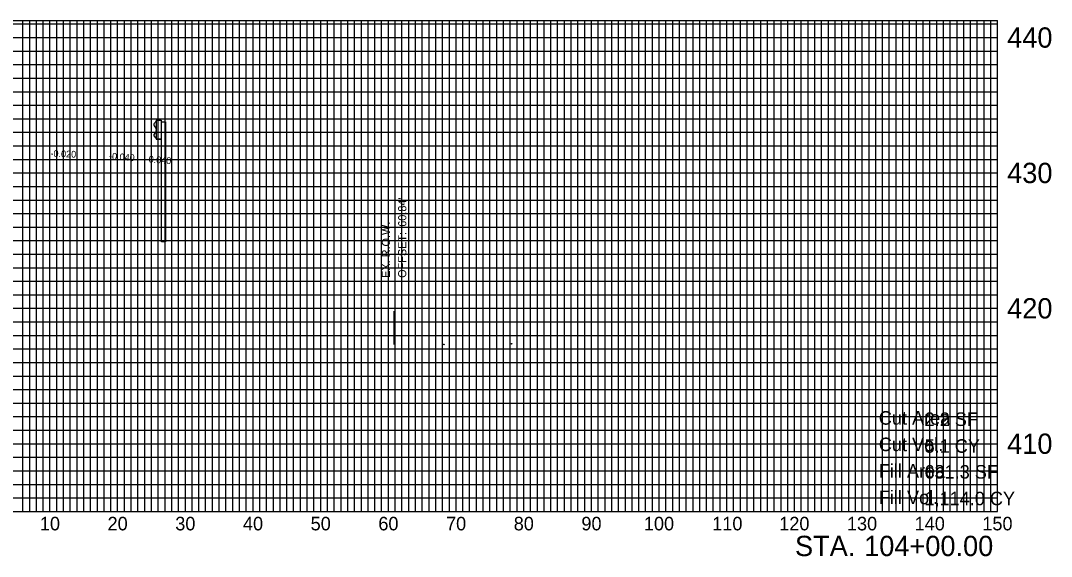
# Model space of a CAD drawing. Extents: x -158 to 158, y 398 to 482.
# Drawn here: x 5.7 to 157.9, y 398.4 to 477.5 of the extents above; entities that cross this region are included whole.
import ezdxf

# ---------------------------------------------------------------- set-up
doc = ezdxf.new("R2010")
doc.units = 0
for name, color, linetype in [('AERIAL - Automatic - Grid Points', 7, 'Continuous'), ('DES - CL - Proposed Text', 7, 'Continuous'), ('DES - SCRATCH - User 1', 7, 'Continuous'), ('DES - SHEET - Corner Text', 7, 'Continuous'), ('DES - SHEET - Revision Text', 7, 'Continuous'), ('DES - SHEET - STAMP - Initial Studies Request', 7, 'Continuous'), ('DES - SHEET - STAMP - ROW Field Review', 7, 'Continuous'), ('SUR - DTM - Spot Points', 7, 'Continuous'), ('SUR - PROPERTY - Tract Numbers', 7, 'Continuous')]:
    doc.layers.add(name, color=color, linetype=linetype)

msp = doc.modelspace()

# ---------------------------------------------------------------- linework, layer by layer
at = {"layer": 'AERIAL - Automatic - Grid Points'}
msp.add_line((60.84, 429.66), (60.84, 434.58), dxfattribs=at)
msp.add_line((60.84, 429.66), (60.84, 434.58), dxfattribs=at)
msp.add_line((60.84, 429.66), (60.84, 434.58), dxfattribs=at)
msp.add_line((60.84, 429.66), (60.84, 434.58), dxfattribs=at)
at = {"layer": 'DES - SCRATCH - User 1'}
for p, q in [((-150, 477.5), (150, 477.5)), ((-150, 477.5), (150, 477.5)), ((-150, 477.5), (150, 477.5)), ((10, 405), (10, 477.5)), ((10, 405), (10, 477.5)), ((10, 405), (10, 477.5)), ((20, 405), (20, 477.5)), ((20, 405), (20, 477.5)), ((20, 405), (20, 477.5)), ((30, 405), (30, 477.5)), ((30, 405), (30, 477.5)), ((30, 405), (30, 477.5)), ((40, 405), (40, 477.5)), ((40, 405), (40, 477.5)), ((40, 405), (40, 477.5)), ((50, 405), (50, 477.5)), ((50, 405), (50, 477.5)), ((50, 405), (50, 477.5)), ((60, 405), (60, 477.5)), ((60, 405), (60, 477.5)), ((60, 405), (60, 477.5)), ((70, 405), (70, 477.5)), ((70, 405), (70, 477.5)), ((70, 405), (70, 477.5)), ((80, 405), (80, 477.5)), ((80, 405), (80, 477.5)), ((80, 405), (80, 477.5)), ((90, 405), (90, 477.5)), ((90, 405), (90, 477.5)), ((90, 405), (90, 477.5)), ((100, 405), (100, 477.5)), ((100, 405), (100, 477.5)), ((100, 405), (100, 477.5)), ((110, 405), (110, 477.5)), ((110, 405), (110, 477.5)), ((110, 405), (110, 477.5)), ((120, 405), (120, 477.5)), ((120, 405), (120, 477.5)), ((120, 405), (120, 477.5)), ((130, 405), (130, 477.5)), ((130, 405), (130, 477.5)), ((130, 405), (130, 477.5)), ((140, 405), (140, 477.5)), ((140, 405), (140, 477.5)), ((140, 405), (140, 477.5)), ((150, 405), (150, 477.5)), ((150, 405), (150, 477.5)), ((150, 405), (150, 477.5)), ((-150, 475), (150, 475)), ((-150, 475), (150, 475)), ((-150, 475), (150, 475)), ((-150, 455), (150, 455)), ((-150, 455), (150, 455)), ((-150, 455), (150, 455)), ((-150, 435), (150, 435)), ((-150, 435), (150, 435)), ((-150, 435), (150, 435)), ((-150, 415), (150, 415)), ((-150, 415), (150, 415)), ((-150, 415), (150, 415)), ((-150, 405), (150, 405)), ((-150, 405), (150, 405)), ((-150, 405), (150, 405))]:
    msp.add_line(p, q, dxfattribs=at)
at = {"layer": 'DES - SHEET - Corner Text'}
for p, q in [((-150, 477), (150, 477)), ((-150, 477), (150, 477)), ((-150, 477), (150, 477)), ((6, 405), (6, 477.5)), ((6, 405), (6, 477.5)), ((6, 405), (6, 477.5)), ((7, 405), (7, 477.5)), ((7, 405), (7, 477.5)), ((7, 405), (7, 477.5)), ((8, 405), (8, 477.5)), ((8, 405), (8, 477.5)), ((8, 405), (8, 477.5)), ((9, 405), (9, 477.5)), ((9, 405), (9, 477.5)), ((9, 405), (9, 477.5)), ((11, 405), (11, 477.5)), ((11, 405), (11, 477.5)), ((11, 405), (11, 477.5)), ((12, 405), (12, 477.5)), ((12, 405), (12, 477.5)), ((12, 405), (12, 477.5)), ((13, 405), (13, 477.5)), ((13, 405), (13, 477.5)), ((13, 405), (13, 477.5)), ((14, 405), (14, 477.5)), ((14, 405), (14, 477.5)), ((14, 405), (14, 477.5)), ((15, 405), (15, 477.5)), ((15, 405), (15, 477.5)), ((15, 405), (15, 477.5)), ((16, 405), (16, 477.5)), ((16, 405), (16, 477.5)), ((16, 405), (16, 477.5)), ((17, 405), (17, 477.5)), ((17, 405), (17, 477.5)), ((17, 405), (17, 477.5)), ((18, 405), (18, 477.5)), ((18, 405), (18, 477.5)), ((18, 405), (18, 477.5)), ((19, 405), (19, 477.5)), ((19, 405), (19, 477.5)), ((19, 405), (19, 477.5)), ((21, 405), (21, 477.5)), ((21, 405), (21, 477.5)), ((21, 405), (21, 477.5)), ((22, 405), (22, 477.5)), ((22, 405), (22, 477.5)), ((22, 405), (22, 477.5)), ((23, 405), (23, 477.5)), ((23, 405), (23, 477.5)), ((23, 405), (23, 477.5)), ((24, 405), (24, 477.5)), ((24, 405), (24, 477.5)), ((24, 405), (24, 477.5)), ((25, 405), (25, 477.5)), ((25, 405), (25, 477.5)), ((25, 405), (25, 477.5)), ((26, 405), (26, 477.5)), ((26, 405), (26, 477.5)), ((26, 405), (26, 477.5)), ((27, 405), (27, 477.5)), ((27, 405), (27, 477.5)), ((27, 405), (27, 477.5)), ((28, 405), (28, 477.5)), ((28, 405), (28, 477.5)), ((28, 405), (28, 477.5)), ((29, 405), (29, 477.5)), ((29, 405), (29, 477.5)), ((29, 405), (29, 477.5)), ((31, 405), (31, 477.5)), ((31, 405), (31, 477.5)), ((31, 405), (31, 477.5)), ((32, 405), (32, 477.5)), ((32, 405), (32, 477.5)), ((32, 405), (32, 477.5)), ((33, 405), (33, 477.5)), ((33, 405), (33, 477.5)), ((33, 405), (33, 477.5)), ((34, 405), (34, 477.5)), ((34, 405), (34, 477.5)), ((34, 405), (34, 477.5)), ((35, 405), (35, 477.5)), ((35, 405), (35, 477.5)), ((35, 405), (35, 477.5)), ((36, 405), (36, 477.5)), ((36, 405), (36, 477.5)), ((36, 405), (36, 477.5)), ((37, 405), (37, 477.5)), ((37, 405), (37, 477.5)), ((37, 405), (37, 477.5)), ((38, 405), (38, 477.5)), ((38, 405), (38, 477.5)), ((38, 405), (38, 477.5)), ((39, 405), (39, 477.5)), ((39, 405), (39, 477.5)), ((39, 405), (39, 477.5)), ((41, 405), (41, 477.5)), ((41, 405), (41, 477.5)), ((41, 405), (41, 477.5)), ((42, 405), (42, 477.5)), ((42, 405), (42, 477.5)), ((42, 405), (42, 477.5)), ((43, 405), (43, 477.5)), ((43, 405), (43, 477.5)), ((43, 405), (43, 477.5)), ((44, 405), (44, 477.5)), ((44, 405), (44, 477.5)), ((44, 405), (44, 477.5)), ((45, 405), (45, 477.5)), ((45, 405), (45, 477.5)), ((45, 405), (45, 477.5)), ((46, 405), (46, 477.5)), ((46, 405), (46, 477.5)), ((46, 405), (46, 477.5)), ((47, 405), (47, 477.5)), ((47, 405), (47, 477.5)), ((47, 405), (47, 477.5)), ((48, 405), (48, 477.5)), ((48, 405), (48, 477.5)), ((49, 405), (49, 477.5)), ((49, 405), (49, 477.5)), ((49, 405), (49, 477.5)), ((51, 405), (51, 477.5)), ((51, 405), (51, 477.5)), ((51, 405), (51, 477.5)), ((52, 405), (52, 477.5)), ((52, 405), (52, 477.5)), ((52, 405), (52, 477.5)), ((53, 405), (53, 477.5)), ((53, 405), (53, 477.5)), ((53, 405), (53, 477.5)), ((54, 405), (54, 477.5)), ((54, 405), (54, 477.5)), ((54, 405), (54, 477.5)), ((55, 405), (55, 477.5)), ((55, 405), (55, 477.5)), ((55, 405), (55, 477.5)), ((56, 405), (56, 477.5)), ((56, 405), (56, 477.5)), ((56, 405), (56, 477.5)), ((57, 405), (57, 477.5)), ((57, 405), (57, 477.5)), ((57, 405), (57, 477.5)), ((58, 405), (58, 477.5)), ((58, 405), (58, 477.5)), ((58, 405), (58, 477.5)), ((59, 405), (59, 477.5)), ((59, 405), (59, 477.5)), ((59, 405), (59, 477.5)), ((61, 405), (61, 477.5)), ((61, 405), (61, 477.5)), ((61, 405), (61, 477.5)), ((62, 405), (62, 477.5)), ((62, 405), (62, 477.5)), ((62, 405), (62, 477.5)), ((63, 405), (63, 477.5)), ((63, 405), (63, 477.5)), ((63, 405), (63, 477.5)), ((64, 405), (64, 477.5)), ((64, 405), (64, 477.5)), ((64, 405), (64, 477.5)), ((65, 405), (65, 477.5)), ((65, 405), (65, 477.5)), ((65, 405), (65, 477.5)), ((66, 405), (66, 477.5)), ((66, 405), (66, 477.5)), ((66, 405), (66, 477.5)), ((67, 405), (67, 477.5)), ((67, 405), (67, 477.5)), ((67, 405), (67, 477.5)), ((68, 405), (68, 477.5)), ((68, 405), (68, 477.5)), ((68, 405), (68, 477.5)), ((69, 405), (69, 477.5)), ((69, 405), (69, 477.5)), ((69, 405), (69, 477.5)), ((71, 405), (71, 477.5)), ((71, 405), (71, 477.5)), ((71, 405), (71, 477.5)), ((72, 405), (72, 477.5)), ((72, 405), (72, 477.5)), ((72, 405), (72, 477.5)), ((73, 405), (73, 477.5)), ((73, 405), (73, 477.5)), ((73, 405), (73, 477.5)), ((74, 405), (74, 477.5)), ((74, 405), (74, 477.5)), ((74, 405), (74, 477.5)), ((75, 405), (75, 477.5)), ((75, 405), (75, 477.5)), ((75, 405), (75, 477.5)), ((76, 405), (76, 477.5)), ((76, 405), (76, 477.5)), ((76, 405), (76, 477.5)), ((77, 405), (77, 477.5)), ((77, 405), (77, 477.5)), ((77, 405), (77, 477.5)), ((78, 405), (78, 477.5)), ((78, 405), (78, 477.5)), ((78, 405), (78, 477.5)), ((79, 405), (79, 477.5)), ((79, 405), (79, 477.5)), ((79, 405), (79, 477.5)), ((81, 405), (81, 477.5)), ((81, 405), (81, 477.5)), ((81, 405), (81, 477.5)), ((82, 405), (82, 477.5)), ((82, 405), (82, 477.5)), ((82, 405), (82, 477.5)), ((83, 405), (83, 477.5)), ((83, 405), (83, 477.5)), ((83, 405), (83, 477.5)), ((84, 405), (84, 477.5)), ((84, 405), (84, 477.5)), ((84, 405), (84, 477.5)), ((85, 405), (85, 477.5)), ((85, 405), (85, 477.5)), ((85, 405), (85, 477.5)), ((86, 405), (86, 477.5)), ((86, 405), (86, 477.5)), ((86, 405), (86, 477.5)), ((87, 405), (87, 477.5)), ((87, 405), (87, 477.5)), ((87, 405), (87, 477.5)), ((88, 405), (88, 477.5)), ((88, 405), (88, 477.5)), ((88, 405), (88, 477.5)), ((89, 405), (89, 477.5)), ((89, 405), (89, 477.5)), ((89, 405), (89, 477.5)), ((91, 405), (91, 477.5)), ((91, 405), (91, 477.5)), ((91, 405), (91, 477.5)), ((92, 405), (92, 477.5)), ((92, 405), (92, 477.5)), ((92, 405), (92, 477.5)), ((93, 405), (93, 477.5)), ((93, 405), (93, 477.5)), ((93, 405), (93, 477.5)), ((94, 405), (94, 477.5)), ((94, 405), (94, 477.5)), ((94, 405), (94, 477.5)), ((95, 405), (95, 477.5)), ((95, 405), (95, 477.5)), ((95, 405), (95, 477.5)), ((96, 405), (96, 477.5)), ((96, 405), (96, 477.5)), ((96, 405), (96, 477.5)), ((97, 405), (97, 477.5)), ((97, 405), (97, 477.5)), ((97, 405), (97, 477.5)), ((98, 405), (98, 477.5)), ((98, 405), (98, 477.5)), ((98, 405), (98, 477.5)), ((99, 405), (99, 477.5)), ((99, 405), (99, 477.5)), ((99, 405), (99, 477.5)), ((101, 405), (101, 477.5)), ((101, 405), (101, 477.5)), ((101, 405), (101, 477.5)), ((102, 405), (102, 477.5)), ((102, 405), (102, 477.5)), ((102, 405), (102, 477.5)), ((103, 405), (103, 477.5)), ((103, 405), (103, 477.5)), ((103, 405), (103, 477.5)), ((104, 405), (104, 477.5)), ((104, 405), (104, 477.5)), ((104, 405), (104, 477.5)), ((105, 405), (105, 477.5)), ((105, 405), (105, 477.5)), ((105, 405), (105, 477.5)), ((106, 405), (106, 477.5)), ((106, 405), (106, 477.5)), ((106, 405), (106, 477.5)), ((107, 405), (107, 477.5)), ((107, 405), (107, 477.5)), ((107, 405), (107, 477.5)), ((108, 405), (108, 477.5)), ((108, 405), (108, 477.5)), ((108, 405), (108, 477.5)), ((109, 405), (109, 477.5)), ((109, 405), (109, 477.5)), ((109, 405), (109, 477.5)), ((111, 405), (111, 477.5)), ((111, 405), (111, 477.5)), ((111, 405), (111, 477.5)), ((112, 405), (112, 477.5)), ((112, 405), (112, 477.5)), ((112, 405), (112, 477.5)), ((113, 405), (113, 477.5)), ((113, 405), (113, 477.5)), ((113, 405), (113, 477.5)), ((114, 405), (114, 477.5)), ((114, 405), (114, 477.5)), ((114, 405), (114, 477.5)), ((115, 405), (115, 477.5)), ((115, 405), (115, 477.5)), ((115, 405), (115, 477.5)), ((116, 405), (116, 477.5)), ((116, 405), (116, 477.5)), ((116, 405), (116, 477.5)), ((117, 405), (117, 477.5)), ((117, 405), (117, 477.5)), ((117, 405), (117, 477.5)), ((118, 405), (118, 477.5)), ((118, 405), (118, 477.5)), ((118, 405), (118, 477.5)), ((119, 405), (119, 477.5)), ((119, 405), (119, 477.5)), ((119, 405), (119, 477.5)), ((121, 405), (121, 477.5)), ((121, 405), (121, 477.5)), ((121, 405), (121, 477.5)), ((122, 405), (122, 477.5)), ((122, 405), (122, 477.5)), ((122, 405), (122, 477.5)), ((123, 405), (123, 477.5)), ((123, 405), (123, 477.5)), ((123, 405), (123, 477.5)), ((124, 405), (124, 477.5)), ((124, 405), (124, 477.5)), ((124, 405), (124, 477.5)), ((125, 405), (125, 477.5)), ((125, 405), (125, 477.5)), ((125, 405), (125, 477.5)), ((126, 405), (126, 477.5)), ((126, 405), (126, 477.5)), ((126, 405), (126, 477.5)), ((127, 405), (127, 477.5)), ((127, 405), (127, 477.5)), ((127, 405), (127, 477.5)), ((128, 405), (128, 477.5)), ((128, 405), (128, 477.5)), ((128, 405), (128, 477.5)), ((129, 405), (129, 477.5)), ((129, 405), (129, 477.5)), ((129, 405), (129, 477.5)), ((131, 405), (131, 477.5)), ((131, 405), (131, 477.5)), ((131, 405), (131, 477.5)), ((132, 405), (132, 477.5)), ((132, 405), (132, 477.5)), ((132, 405), (132, 477.5)), ((133, 405), (133, 477.5)), ((133, 405), (133, 477.5)), ((133, 405), (133, 477.5)), ((134, 405), (134, 477.5)), ((134, 405), (134, 477.5)), ((134, 405), (134, 477.5)), ((135, 405), (135, 477.5)), ((135, 405), (135, 477.5)), ((135, 405), (135, 477.5)), ((136, 405), (136, 477.5)), ((136, 405), (136, 477.5)), ((136, 405), (136, 477.5)), ((137, 405), (137, 477.5)), ((137, 405), (137, 477.5)), ((137, 405), (137, 477.5)), ((138, 405), (138, 477.5)), ((138, 405), (138, 477.5)), ((138, 405), (138, 477.5)), ((139, 405), (139, 477.5)), ((139, 405), (139, 477.5)), ((139, 405), (139, 477.5)), ((141, 405), (141, 477.5)), ((141, 405), (141, 477.5)), ((141, 405), (141, 477.5)), ((142, 405), (142, 477.5)), ((142, 405), (142, 477.5)), ((142, 405), (142, 477.5)), ((143, 405), (143, 477.5)), ((143, 405), (143, 477.5)), ((143, 405), (143, 477.5)), ((144, 405), (144, 477.5)), ((144, 405), (144, 477.5)), ((144, 405), (144, 477.5)), ((145, 405), (145, 477.5)), ((145, 405), (145, 477.5)), ((145, 405), (145, 477.5)), ((146, 405), (146, 477.5)), ((146, 405), (146, 477.5)), ((146, 405), (146, 477.5)), ((147, 405), (147, 477.5)), ((147, 405), (147, 477.5)), ((147, 405), (147, 477.5)), ((148, 405), (148, 477.5)), ((148, 405), (148, 477.5)), ((148, 405), (148, 477.5)), ((149, 405), (149, 477.5)), ((149, 405), (149, 477.5)), ((149, 405), (149, 477.5)), ((-150, 473), (150, 473)), ((-150, 473), (150, 473)), ((-150, 473), (150, 473)), ((-150, 471), (150, 471)), ((-150, 471), (150, 471)), ((-150, 471), (150, 471)), ((-150, 469), (150, 469)), ((-150, 469), (150, 469)), ((-150, 469), (150, 469)), ((-150, 467), (150, 467)), ((-150, 467), (150, 467)), ((-150, 467), (150, 467)), ((-150, 465), (150, 465)), ((-150, 465), (150, 465)), ((-150, 465), (150, 465)), ((-150, 463), (150, 463)), ((-150, 463), (150, 463)), ((-150, 463), (150, 463)), ((-150, 461), (150, 461)), ((-150, 461), (150, 461)), ((-150, 461), (150, 461)), ((-150, 459), (150, 459)), ((-150, 459), (150, 459)), ((-150, 459), (150, 459)), ((-150, 457), (150, 457)), ((-150, 457), (150, 457)), ((-150, 457), (150, 457)), ((-150, 453), (150, 453)), ((-150, 453), (150, 453)), ((-150, 453), (150, 453)), ((-150, 451), (150, 451)), ((-150, 451), (150, 451)), ((-150, 451), (150, 451)), ((-150, 449), (150, 449)), ((-150, 449), (150, 449)), ((-150, 449), (150, 449)), ((-150, 447), (150, 447)), ((-150, 447), (150, 447)), ((-150, 447), (150, 447)), ((-150, 445), (150, 445)), ((-150, 445), (150, 445)), ((-150, 445), (150, 445)), ((-150, 443), (150, 443)), ((-150, 443), (150, 443)), ((-150, 443), (150, 443)), ((-150, 441), (150, 441)), ((-150, 441), (150, 441)), ((-150, 441), (150, 441)), ((-150, 439), (150, 439)), ((-150, 439), (150, 439)), ((-150, 439), (150, 439)), ((-150, 437), (150, 437)), ((-150, 437), (150, 437)), ((-150, 437), (150, 437)), ((-150, 433), (150, 433)), ((-150, 433), (150, 433)), ((-150, 433), (150, 433)), ((-150, 431), (150, 431)), ((-150, 431), (150, 431)), ((-150, 431), (150, 431)), ((-150, 429), (150, 429)), ((-150, 429), (150, 429)), ((-150, 429), (150, 429)), ((-150, 427), (150, 427)), ((-150, 427), (150, 427)), ((-150, 427), (150, 427)), ((-150, 425), (150, 425)), ((-150, 425), (150, 425)), ((-150, 425), (150, 425)), ((-150, 423), (150, 423)), ((-150, 423), (150, 423)), ((-150, 423), (150, 423)), ((-150, 421), (150, 421)), ((-150, 421), (150, 421)), ((-150, 421), (150, 421)), ((-150, 419), (150, 419)), ((-150, 419), (150, 419)), ((-150, 419), (150, 419)), ((-150, 417), (150, 417)), ((-150, 417), (150, 417)), ((-150, 417), (150, 417)), ((-150, 413), (150, 413)), ((-150, 413), (150, 413)), ((-150, 413), (150, 413)), ((-150, 411), (150, 411)), ((-150, 411), (150, 411)), ((-150, 411), (150, 411)), ((-150, 409), (150, 409)), ((-150, 409), (150, 409)), ((-150, 409), (150, 409)), ((-150, 407), (150, 407)), ((-150, 407), (150, 407)), ((-150, 407), (150, 407))]:
    msp.add_line(p, q, dxfattribs=at)
at = {"layer": 'SUR - DTM - Spot Points'}
for p, q in [((25.53, 462.47), (25.4, 462.29)), ((25.4, 461.98), (25.65, 461.63)), ((25.69, 462.59), (25.65, 462.57)), ((25.69, 461.47), (25.69, 461.25)), ((25.7, 462.78), (25.7, 462.78)), ((25.7, 462.78), (26.45, 462.78)), ((26.45, 462.78), (25.7, 462.78)), ((25.7, 462.78), (25.7, 459.98)), ((25.7, 462.78), (25.7, 459.98)), ((26.45, 462.78), (26.45, 462.78)), ((26.45, 462.78), (26.45, 459.98)), ((26.45, 462.78), (26.45, 459.98)), ((25.65, 461.09), (25.4, 460.74)), ((25.4, 460.43), (25.53, 460.25)), ((25.65, 460.15), (25.69, 460.14)), ((25.7, 459.98), (25.7, 459.98)), ((25.7, 459.98), (26.45, 459.98)), ((26.45, 459.98), (25.7, 459.98)), ((26.45, 459.98), (26.45, 459.98))]:
    msp.add_line(p, q, dxfattribs=at)
msp.add_lwpolyline([(26.47, 462.56), (27.09, 462.56), (27.09, 444.8), (26.47, 444.8)], close=True, dxfattribs=at)
for centre, major_axis, start_param, end_param in [((25.45, 462.13), (0, 0.188), 0.610865, 2.530727), ((25.71, 461.98), (0, 0.6), 0.174533, 0.610865), ((25.6, 461.47), (0, 0.188), 4.712389, 5.67232), ((25.45, 460.59), (0, 0.188), 0.610865, 2.530727), ((25.71, 460.74), (0, -0.6), 5.67232, 6.108652), ((25.6, 461.25), (0, 0.188), 3.752458, 4.712389)]:
    msp.add_ellipse(centre, major_axis=major_axis, ratio=0.5, start_param=start_param, end_param=end_param, dxfattribs=at)
at = {"layer": 'SUR - PROPERTY - Tract Numbers'}
for centre in [(68.19, 429.67), (78.19, 429.77)]:
    msp.add_circle(centre, 0.05, dxfattribs=at)

# ---------------------------------------------------------------- texts
at = {"layer": 'AERIAL - Automatic - Grid Points'}
for s, p in [("60.84'", (62.64, 447.05)), ("60.84'", (62.64, 447.05)), ("60.84'", (62.64, 447.05)), ("60.84'", (62.64, 447.05)), ('EX. R.O.W. ', (60.24, 439.5)), ('EX. R.O.W. ', (60.24, 439.5)), ('EX. R.O.W. ', (60.24, 439.5)), ('EX. R.O.W. ', (60.24, 439.5)), ('OFFSET: ', (62.64, 439.5)), ('OFFSET: ', (62.64, 439.5)), ('OFFSET: ', (62.64, 439.5)), ('OFFSET: ', (62.64, 439.5))]:
    msp.add_text(s, height=1.2, rotation=90, dxfattribs=at).set_placement(p)
at = {"layer": 'DES - CL - Proposed Text'}
for s, rotation, p in [('-0.020', 357.7094, (10.06, 457.4)), ('-0.020', 357.7094, (10.06, 457.4)), ('-0.020', 357.7094, (10.06, 457.4)), ('-0.040', 355.4261, (18.69, 457.02)), ('-0.040', 355.4261, (18.69, 457.02)), ('-0.040', 355.4261, (18.69, 457.02)), ('-0.040', 355.4261, (24.1, 456.59))]:
    msp.add_text(s, height=1, rotation=rotation, dxfattribs=at).set_placement(p)
at = {"layer": 'DES - SHEET - Revision Text'}
for s, height, p in [('440', 3, (151.41, 473.5)), ('440', 3, (151.41, 473.5)), ('440', 3, (151.41, 473.5)), ('430', 3, (151.41, 453.5)), ('430', 3, (151.41, 453.5)), ('430', 3, (151.41, 453.5)), ('420', 3, (151.41, 433.5)), ('420', 3, (151.41, 433.5)), ('420', 3, (151.41, 433.5)), ('410', 3, (151.41, 413.5)), ('410', 3, (151.41, 413.5)), ('410', 3, (151.41, 413.5)), ('10', 2, (8.51, 402.2)), ('10', 2, (8.51, 402.2)), ('10', 2, (8.51, 402.2)), ('20', 2, (18.51, 402.2)), ('20', 2, (18.51, 402.2)), ('20', 2, (18.51, 402.2)), ('30', 2, (28.51, 402.2)), ('30', 2, (28.51, 402.2)), ('30', 2, (28.51, 402.2)), ('40', 2, (38.51, 402.2)), ('40', 2, (38.51, 402.2)), ('40', 2, (38.51, 402.2)), ('50', 2, (48.51, 402.2)), ('50', 2, (48.51, 402.2)), ('50', 2, (48.51, 402.2)), ('60', 2, (58.51, 402.2)), ('60', 2, (58.51, 402.2)), ('60', 2, (58.51, 402.2)), ('70', 2, (68.51, 402.2)), ('70', 2, (68.51, 402.2)), ('70', 2, (68.51, 402.2)), ('80', 2, (78.51, 402.2)), ('80', 2, (78.51, 402.2)), ('80', 2, (78.51, 402.2)), ('90', 2, (88.51, 402.2)), ('90', 2, (88.51, 402.2)), ('90', 2, (88.51, 402.2)), ('100', 2, (97.74, 402.2)), ('100', 2, (97.74, 402.2)), ('100', 2, (97.74, 402.2)), ('110', 2, (107.84, 402.2)), ('110', 2, (107.84, 402.2)), ('110', 2, (107.84, 402.2)), ('120', 2, (117.74, 402.2)), ('120', 2, (117.74, 402.2)), ('120', 2, (117.74, 402.2)), ('130', 2, (127.74, 402.2)), ('130', 2, (127.74, 402.2)), ('130', 2, (127.74, 402.2)), ('140', 2, (137.74, 402.2)), ('140', 2, (137.74, 402.2)), ('140', 2, (137.74, 402.2)), ('150', 2, (147.74, 402.2)), ('150', 2, (147.74, 402.2)), ('150', 2, (147.74, 402.2)), (' STA. ', 3, (118.95, 398.4)), (' STA. ', 3, (118.95, 398.4)), (' STA. ', 3, (118.95, 398.4)), ('104+00.00', 3, (130.28, 398.4)), ('104+00.00', 3, (130.28, 398.4)), ('104+00.00', 3, (130.28, 398.4))]:
    msp.add_text(s, height=height, dxfattribs=at).set_placement(p)
at = {"layer": 'DES - SHEET - STAMP - Initial Studies Request'}
for s, p in [('Cut Area', (132.45, 417.81)), ('2.2 SF', (139.21, 417.62)), ('Cut Vol.', (132.45, 413.9)), ('5.1 CY', (139.21, 413.66))]:
    msp.add_text(s, height=2, dxfattribs=at).set_placement(p)
at = {"layer": 'DES - SHEET - STAMP - ROW Field Review'}
for s, p in [('Fill Area', (132.45, 409.99)), ('631.3 SF', (139.19, 409.85)), ('Fill Vol.', (132.45, 406.08)), ('1,114.0 CY', (139.19, 405.91))]:
    msp.add_text(s, height=2, dxfattribs=at).set_placement(p)

doc.saveas('drawing.dxf')
